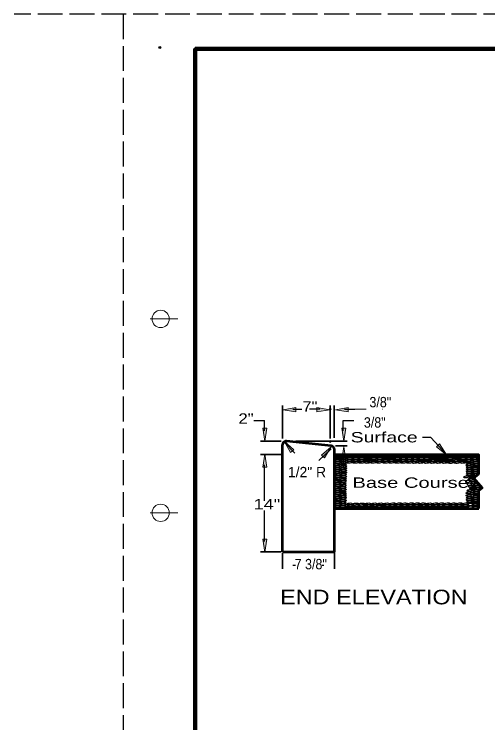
# Model space of a CAD drawing. Extents: x 75.6 to 110.9, y 28 to 50.
# Drawn here: x 75.6 to 82.44, y 39.75 to 49.98 of the extents above; entities that cross this region are included whole.
import ezdxf

# ---------------------------------------------------------------- set-up
doc = ezdxf.new("R2010")
doc.units = 0
doc.header["$LTSCALE"] = 0.06
doc.header["$PDMODE"] = 32
doc.header["$PDSIZE"] = 0.03
doc.linetypes.add('LONG_DASHED', pattern=[7.5, 6, -1.5])
doc.layers.add('1', color=7, linetype='Continuous', lineweight=25)
doc.layers.add('3', color=7, linetype='Continuous', lineweight=13)

msp = doc.modelspace()

# ---------------------------------------------------------------- hatches: boundary and pattern name
at = {"layer": '3'}
for points in [[(79.67092, 44.3), (79.67092, 44.2385), (79.48633, 44.26933), (79.48633, 44.26933)], [(79.97408, 44.3), (79.97408, 44.2385), (80.15867, 44.26933), (80.15867, 44.26933)], [(80.42625, 44.3), (80.42625, 44.2385), (80.24167, 44.26933), (80.24167, 44.26933)], [(79.19092, 44.00033), (79.25242, 44.00033), (79.22158, 43.81575), (79.22158, 43.81575)], [(80.39358, 44.00033), (80.33208, 44.00033), (80.36292, 43.81575), (80.36292, 43.81575)], [(79.594, 43.65142), (79.64158, 43.69058), (79.5005, 43.81358), (79.5005, 43.81358)], [(80.08542, 43.57192), (80.03875, 43.61192), (80.18192, 43.73242), (80.18192, 43.73242)], [(80.39358, 43.547), (80.33208, 43.547), (80.36292, 43.73158), (80.36292, 43.73158)], [(81.69967, 43.73425), (81.74517, 43.77558), (81.84642, 43.61825), (81.84642, 43.61825)], [(79.19092, 43.44117), (79.25242, 43.44117), (79.22158, 43.62575), (79.22158, 43.62575)], [(79.19092, 42.39817), (79.25242, 42.39817), (79.22158, 42.21358), (79.22158, 42.21358)], [(79.19092, 42.39817), (79.25242, 42.39817), (79.22158, 42.21358), (79.22158, 42.21358)]]:
    msp.add_hatch(color=256, dxfattribs=at).paths.add_polyline_path(points)

# ---------------------------------------------------------------- linework, layer by layer
at = {"layer": '1', "linetype": 'LONG_DASHED'}
for p, q in [((110.8, 49.97992), (75.6, 49.97992)), ((77.175, 49.97992), (77.175, 27.97992))]:
    msp.add_line(p, q, dxfattribs=at)
at = {"layer": '1', "lineweight": 158}
for p, q in [((78.21667, 49.47992), (78.21667, 28.47992)), ((110.71667, 49.47992), (78.21667, 49.47992))]:
    msp.add_line(p, q, dxfattribs=at)
at = {"layer": '1', "lineweight": 13}
for p, q in [((77.96667, 45.57992), (77.56667, 45.57992)), ((80.226, 43.61183), (82.31042, 43.61183)), ((80.226, 43.58358), (82.31042, 43.58358)), ((77.96667, 42.77992), (77.56667, 42.77992))]:
    msp.add_line(p, q, dxfattribs=at)
at = {"layer": '1', "lineweight": 53}
for p, q in [((80.1775, 43.74758), (79.53667, 43.8145)), ((79.47725, 42.21767), (79.47725, 43.76075)), ((80.226, 43.59875), (82.31042, 43.59875)), ((82.3115, 42.83717), (80.22708, 42.83717))]:
    msp.add_line(p, q, dxfattribs=at)
for points in [[(79.47725, 42.21767), (80.226, 42.21767), (80.226, 43.69392)], [(80.226, 43.62408), (82.31042, 43.62408), (82.31042, 43.33558)], [(82.31042, 43.33558), (82.24275, 43.27817), (82.36375, 43.14133), (82.31042, 43.09667), (82.31042, 42.84492)]]:
    msp.add_lwpolyline(points, dxfattribs=at)
at = {"layer": '1', "lineweight": 13}
for centre in [(77.71667, 45.57992), (77.71667, 42.77992)]:
    msp.add_circle(centre, 0.125, dxfattribs=at)
at = {"layer": '1', "lineweight": 53}
for centre, start, end in [((79.53125, 43.76075), 84.18493, 180), ((80.172, 43.6939), 0, 84.18493)]:
    msp.add_arc(centre, 0.054, start, end, dxfattribs=at)
at = {"layer": '1'}
for centre, major_axis, ratio in [((80.26817, 43.47475), (0.04401, 0.00432), 0.308638), ((80.27033, 43.536), (0.04401, 0.00432), 0.308638), ((80.27033, 43.50542), (0.04401, 0.00432), 0.308638), ((80.27133, 43.56667), (0.04401, 0.00432), 0.308638), ((80.35475, 43.56567), (0.04401, 0.00432), 0.308638), ((80.35683, 43.53608), (0.04401, 0.00432), 0.308638), ((80.35683, 43.50758), (0.04401, 0.00432), 0.308638), ((80.35683, 43.48008), (0.04401, 0.00432), 0.308638), ((80.44442, 43.56775), (0.04401, 0.00432), 0.308638), ((80.4455, 43.53925), (0.04401, 0.00432), 0.308638), ((80.4465, 43.51075), (0.04401, 0.00432), 0.308638), ((80.532, 43.56775), (0.04401, 0.00432), 0.308638), ((80.532, 43.50975), (0.04401, 0.00432), 0.308638), ((80.53308, 43.53925), (0.04401, 0.00432), 0.308638), ((80.61858, 43.56775), (0.04401, 0.00432), 0.308638), ((80.61858, 43.50975), (0.04401, 0.00432), 0.308638), ((80.61958, 43.53925), (0.04401, 0.00432), 0.308638), ((80.70408, 43.56667), (0.04401, 0.00432), 0.308638), ((80.70408, 43.50867), (0.04401, 0.00432), 0.308638), ((80.70508, 43.53817), (0.04401, 0.00432), 0.308638), ((80.79058, 43.53817), (0.04401, 0.00432), 0.308638), ((80.79167, 43.56775), (0.04401, 0.00432), 0.308638), ((80.79267, 43.51075), (0.04401, 0.00432), 0.308638), ((80.87717, 43.56775), (0.04401, 0.00432), 0.308638), ((80.87925, 43.53925), (0.04401, 0.00432), 0.308638), ((80.88133, 43.51183), (0.04401, 0.00432), 0.308638), ((80.96158, 43.56667), (0.04401, 0.00432), 0.308638), ((80.96475, 43.54025), (0.04401, 0.00432), 0.308638), ((80.96683, 43.50975), (0.04401, 0.00432), 0.308638), ((81.046, 43.56667), (0.04401, 0.00432), 0.308638), ((81.05025, 43.53925), (0.04401, 0.00432), 0.308638), ((81.05342, 43.51075), (0.04401, 0.00432), 0.308638), ((81.13258, 43.56775), (0.04401, 0.00432), 0.308638), ((81.13575, 43.53817), (0.04401, 0.00432), 0.308638), ((81.13992, 43.50975), (0.04401, 0.00432), 0.308638), ((81.217, 43.56775), (0.04401, 0.00432), 0.308638), ((81.22017, 43.54025), (0.04401, 0.00432), 0.308638), ((81.22333, 43.50975), (0.04401, 0.00432), 0.308638), ((81.30675, 43.56783), (0.04401, 0.00432), 0.308638), ((81.30883, 43.53933), (0.04401, 0.00432), 0.308638), ((81.30992, 43.50975), (0.04401, 0.00432), 0.308638), ((81.39117, 43.50875), (0.04401, 0.00432), 0.308638), ((81.39325, 43.53933), (0.04401, 0.00432), 0.308638), ((81.39433, 43.56892), (0.04401, 0.00432), 0.308638), ((81.47875, 43.50875), (0.04401, 0.00432), 0.308638), ((81.48083, 43.56783), (0.04401, 0.00432), 0.308638), ((81.48083, 43.53825), (0.04401, 0.00432), 0.308638), ((81.56425, 43.50875), (0.04401, 0.00432), 0.308638), ((81.56525, 43.53825), (0.04401, 0.00432), 0.308638), ((81.56633, 43.56575), (0.04401, 0.00432), 0.308638), ((81.65183, 43.56683), (0.04401, 0.00432), 0.308638), ((81.65183, 43.53933), (0.04401, 0.00432), 0.308638), ((81.65183, 43.50875), (0.04401, 0.00432), 0.308638), ((81.73625, 43.56683), (0.04401, 0.00432), 0.308638), ((81.73733, 43.53825), (0.04401, 0.00432), 0.308638), ((81.73842, 43.50875), (0.04401, 0.00432), 0.308638), ((81.82175, 43.56683), (0.04401, 0.00432), 0.308638), ((81.82283, 43.53825), (0.04401, 0.00432), 0.308638), ((81.82383, 43.50875), (0.04401, 0.00432), 0.308638), ((81.90617, 43.56575), (0.04401, 0.00432), 0.308638), ((81.90933, 43.53825), (0.04401, 0.00432), 0.308638), ((81.91042, 43.50767), (0.04401, 0.00432), 0.308638), ((81.99483, 43.56683), (0.04401, 0.00432), 0.308638), ((81.998, 43.53725), (0.04401, 0.00432), 0.308638), ((82.00008, 43.50767), (0.04401, 0.00432), 0.308638), ((82.08242, 43.56783), (0.04401, 0.00432), 0.308638), ((82.08558, 43.53825), (0.04401, 0.00432), 0.308638), ((82.08667, 43.50875), (0.04401, 0.00432), 0.308638), ((82.16792, 43.56567), (0.04401, 0.00432), 0.308638), ((82.17, 43.53508), (0.04401, 0.00432), 0.308638), ((82.17108, 43.47383), (0.04401, 0.00432), 0.308638), ((82.17217, 43.50442), (0.04401, 0.00432), 0.308638), ((82.25658, 43.56567), (0.04401, 0.00432), 0.308638), ((82.25975, 43.53608), (0.04401, 0.00432), 0.308638), ((82.263, 43.47592), (0.04401, 0.00432), 0.308638), ((82.264, 43.5055), (0.04401, 0.00432), 0.308638), ((80.27033, 43.44417), (0.04401, 0.00432), 0.308638), ((80.27033, 43.41458), (0.04401, 0.00432), 0.308638), ((80.27033, 43.38608), (0.04401, 0.00432), 0.308638), ((80.35792, 43.39033), (0.04401, 0.00432), 0.308638), ((80.359, 43.422), (0.04401, 0.00432), 0.308638), ((80.36, 43.4505), (0.04401, 0.00432), 0.308638), ((82.17425, 43.44325), (0.04401, 0.00432), 0.308638), ((82.17525, 43.41475), (0.04401, 0.00432), 0.308638), ((82.17742, 43.38617), (0.04401, 0.00432), 0.308638), ((82.264, 43.44633), (0.04401, 0.00432), 0.308638), ((82.264, 43.41675), (0.04401, 0.00432), 0.308638), ((82.26508, 43.38717), (0.04401, 0.00432), 0.308638), ((80.26925, 43.3565), (0.04401, 0.00432), 0.308638), ((80.26925, 43.327), (0.04401, 0.00432), 0.308638), ((80.27033, 43.29842), (0.04401, 0.00432), 0.308638), ((80.27133, 43.26892), (0.04401, 0.00432), 0.308638), ((80.35683, 43.32908), (0.04401, 0.00432), 0.308638), ((80.35683, 43.2985), (0.04401, 0.00432), 0.308638), ((80.35683, 43.26783), (0.04401, 0.00432), 0.308638), ((80.359, 43.35975), (0.04401, 0.00432), 0.308638), ((82.13625, 43.29958), (0.04401, 0.00432), 0.308638), ((82.17525, 43.32917), (0.04401, 0.00432), 0.308638), ((82.1795, 43.35875), (0.04401, 0.00432), 0.308638), ((82.19967, 43.26683), (0.04401, 0.00432), 0.308638), ((82.22075, 43.29742), (0.04401, 0.00432), 0.308638), ((82.25667, 43.327), (0.04401, 0.00432), 0.308638), ((82.26508, 43.35767), (0.04401, 0.00432), 0.308638), ((80.27033, 43.20867), (0.04401, 0.00432), 0.308638), ((80.27033, 43.17808), (0.04401, 0.00432), 0.308638), ((80.27133, 43.23933), (0.04401, 0.00432), 0.308638), ((80.35267, 43.20558), (0.04401, 0.00432), 0.308638), ((80.35267, 43.17283), (0.04401, 0.00432), 0.308638), ((80.35683, 43.23725), (0.04401, 0.00432), 0.308638), ((82.15167, 43.23267), (0.02825, 0.00619), 0.672605), ((82.178, 43.19258), (0.02825, 0.00619), 0.672605), ((82.225, 43.24258), (0.04401, 0.00432), 0.308638), ((82.24608, 43.21508), (0.04401, 0.00432), 0.308638), ((82.2725, 43.18975), (0.04401, 0.00432), 0.308638), ((82.29358, 43.16442), (0.04401, 0.00432), 0.308638), ((80.27033, 43.1475), (0.04401, 0.00432), 0.308638), ((80.27133, 43.11792), (0.04401, 0.00432), 0.308638), ((80.27133, 43.08725), (0.04401, 0.00432), 0.308638), ((80.35267, 43.14225), (0.04401, 0.00432), 0.308638), ((80.35267, 43.081), (0.04401, 0.00432), 0.308638), ((80.35367, 43.11158), (0.04401, 0.00432), 0.308638), ((82.17108, 43.06942), (0.04401, 0.00432), 0.308638), ((82.18583, 43.10325), (0.04401, 0.00432), 0.308638), ((82.20375, 43.16233), (0.04401, 0.00432), 0.308638), ((82.22275, 43.13383), (0.04401, 0.00432), 0.308638), ((82.263, 43.07675), (0.04401, 0.00432), 0.308638), ((82.27667, 43.10742), (0.04401, 0.00432), 0.308638), ((82.31367, 43.138), (0.04401, 0.00432), 0.308638), ((80.27033, 43.05775), (0.04401, 0.00432), 0.308638), ((80.27242, 43.02708), (0.04401, 0.00432), 0.308638), ((80.27242, 42.9965), (0.04401, 0.00432), 0.308638), ((80.27242, 42.96583), (0.04401, 0.00432), 0.308638), ((80.35367, 43.05142), (0.04401, 0.00432), 0.308638), ((80.35367, 43.02075), (0.04401, 0.00432), 0.308638), ((80.35367, 42.95958), (0.04401, 0.00432), 0.308638), ((80.35475, 42.99125), (0.04401, 0.00432), 0.308638), ((82.17208, 43.03567), (0.04401, 0.00432), 0.308638), ((82.17633, 43.00083), (0.04401, 0.00432), 0.308638), ((82.17842, 42.96917), (0.04401, 0.00432), 0.308638), ((82.264, 43.04717), (0.04401, 0.00432), 0.308638), ((82.264, 42.98808), (0.04401, 0.00432), 0.308638), ((82.26617, 43.01658), (0.04401, 0.00432), 0.308638), ((82.26717, 42.9585), (0.04401, 0.00432), 0.308638), ((80.27033, 42.87608), (0.04401, 0.00432), 0.308638), ((80.27133, 42.93417), (0.04401, 0.00432), 0.308638), ((80.27133, 42.90358), (0.04401, 0.00432), 0.308638), ((80.35158, 42.92892), (0.04401, 0.00432), 0.308638), ((80.35475, 42.90042), (0.04401, 0.00432), 0.308638), ((80.35475, 42.87292), (0.04401, 0.00432), 0.308638), ((80.4455, 42.90783), (0.04401, 0.00432), 0.308638), ((80.4455, 42.87933), (0.04401, 0.00432), 0.308638), ((80.53417, 42.87933), (0.04401, 0.00432), 0.308638), ((80.53517, 42.90683), (0.04401, 0.00432), 0.308638), ((80.62283, 42.88033), (0.04401, 0.00432), 0.308638), ((80.62383, 42.90683), (0.04401, 0.00432), 0.308638), ((80.71042, 42.90783), (0.04401, 0.00432), 0.308638), ((80.71042, 42.87933), (0.04401, 0.00432), 0.308638), ((80.799, 42.90783), (0.04401, 0.00432), 0.308638), ((80.80117, 42.87933), (0.04401, 0.00432), 0.308638), ((80.88875, 42.90783), (0.04401, 0.00432), 0.308638), ((80.88883, 42.87825), (0.04401, 0.00432), 0.308638), ((80.97742, 42.90783), (0.04401, 0.00432), 0.308638), ((80.97742, 42.87933), (0.04401, 0.00432), 0.308638), ((81.064, 42.88033), (0.04401, 0.00432), 0.308638), ((81.06608, 42.91), (0.04401, 0.00432), 0.308638), ((81.15058, 42.88033), (0.04401, 0.00432), 0.308638), ((81.15475, 42.91), (0.04401, 0.00432), 0.308638), ((81.23917, 42.90892), (0.04401, 0.00432), 0.308638), ((81.24133, 42.88042), (0.04401, 0.00432), 0.308638), ((81.32883, 42.91), (0.04401, 0.00432), 0.308638), ((81.32892, 42.8815), (0.04401, 0.00432), 0.308638), ((81.41542, 42.91), (0.04401, 0.00432), 0.308638), ((81.41542, 42.8815), (0.04401, 0.00432), 0.308638), ((81.503, 42.90892), (0.04401, 0.00432), 0.308638), ((81.50408, 42.87933), (0.04401, 0.00432), 0.308638), ((81.59275, 42.90783), (0.04401, 0.00432), 0.308638), ((81.59275, 42.87933), (0.04401, 0.00432), 0.308638), ((81.68142, 42.91), (0.04401, 0.00432), 0.308638), ((81.68142, 42.87933), (0.04401, 0.00432), 0.308638), ((81.76692, 42.88042), (0.04401, 0.00432), 0.308638), ((81.76792, 42.91), (0.04401, 0.00432), 0.308638), ((81.8555, 42.91), (0.04401, 0.00432), 0.308638), ((81.85558, 42.88258), (0.04401, 0.00432), 0.308638), ((81.94417, 42.88042), (0.04401, 0.00432), 0.308638), ((81.94525, 42.90892), (0.04401, 0.00432), 0.308638), ((82.02867, 42.8815), (0.04401, 0.00432), 0.308638), ((82.03175, 42.91), (0.04401, 0.00432), 0.308638), ((82.11942, 42.8815), (0.04401, 0.00432), 0.308638), ((82.1215, 42.91), (0.04401, 0.00432), 0.308638), ((82.18058, 42.9385), (0.04401, 0.00432), 0.308638), ((82.19183, 42.90225), (0.02825, 0.00619), 0.672605), ((82.19283, 42.861), (0.02825, 0.00619), 0.672605), ((82.26183, 42.89625), (0.04401, 0.00432), 0.308638), ((82.26292, 42.92692), (0.04401, 0.00432), 0.308638), ((82.26392, 42.8625), (0.04401, 0.00432), 0.308638), ((80.2735, 42.85075), (0.04401, 0.00432), 0.308638), ((80.359, 42.84975), (0.04401, 0.00432), 0.308638), ((80.44658, 42.85183), (0.04401, 0.00432), 0.308638), ((80.53417, 42.85292), (0.04401, 0.00432), 0.308638), ((80.62283, 42.85292), (0.04401, 0.00432), 0.308638), ((80.7115, 42.85292), (0.04401, 0.00432), 0.308638), ((80.80117, 42.85183), (0.04401, 0.00432), 0.308638), ((80.88883, 42.85075), (0.04401, 0.00432), 0.308638), ((80.97958, 42.85183), (0.04401, 0.00432), 0.308638), ((81.06717, 42.85292), (0.04401, 0.00432), 0.308638), ((81.15367, 42.85392), (0.04401, 0.00432), 0.308638), ((81.24017, 42.85183), (0.04401, 0.00432), 0.308638), ((81.32892, 42.853), (0.04401, 0.00432), 0.308638), ((81.41442, 42.853), (0.04401, 0.00432), 0.308638), ((81.50308, 42.85083), (0.04401, 0.00432), 0.308638), ((81.59067, 42.85083), (0.04401, 0.00432), 0.308638), ((81.68042, 42.85192), (0.04401, 0.00432), 0.308638), ((81.76692, 42.85192), (0.04401, 0.00432), 0.308638), ((81.8535, 42.853), (0.04401, 0.00432), 0.308638), ((81.94425, 42.85192), (0.04401, 0.00432), 0.308638), ((82.02867, 42.853), (0.04401, 0.00432), 0.308638), ((82.1205, 42.853), (0.04401, 0.00432), 0.308638)]:
    msp.add_ellipse(centre, major_axis=major_axis, ratio=ratio, dxfattribs=at)
for p in [(77.70467, 49.49992), (78.21667, 49.47992)]:
    msp.add_point(p, dxfattribs=at)
at = {"layer": '3', "lineweight": 35}
for p, q in [((79.47625, 43.8515), (79.47625, 44.32992)), ((80.16592, 43.85533), (80.16592, 44.32992)), ((80.22267, 43.86283), (80.22267, 44.32992)), ((79.4575, 43.81358), (79.16075, 43.81358)), ((79.6695, 43.81358), (80.40933, 43.81358)), ((80.24142, 43.74542), (80.40933, 43.74542)), ((79.4575, 43.62417), (79.16075, 43.62417)), ((79.4585, 42.21767), (79.16075, 42.21767)), ((79.47725, 42.19892), (79.47725, 41.97108)), ((80.226, 42.19892), (80.226, 41.97108))]:
    msp.add_line(p, q, dxfattribs=at)
at = {"layer": '3', "lineweight": 25}
for p, q in [((79.62625, 44.27592), (79.75567, 44.27592)), ((80.01592, 44.27592), (79.86592, 44.27592)), ((80.37267, 44.27592), (80.52267, 44.27592)), ((79.06475, 44.11358), (79.21475, 44.11358)), ((79.21475, 43.96358), (79.21475, 44.11358)), ((79.49808, 43.80342), (79.65433, 43.64308)), ((80.17875, 43.70492), (80.00175, 43.537)), ((80.35533, 43.59542), (80.35533, 43.44542)), ((79.21475, 42.95317), (79.21475, 43.47417)), ((79.21475, 42.36767), (79.21475, 42.81367)), ((79.62725, 42.02508), (79.66558, 42.02508)), ((80.04858, 42.02508), (80.076, 42.02508))]:
    msp.add_line(p, q, dxfattribs=at)
at = {"layer": '3'}
for p, q in [((79.91158, 44.27592), (80.01592, 44.27592)), ((80.16592, 44.25717), (80.16592, 44.22192)), ((80.22267, 44.27592), (80.22275, 44.27592)), ((80.52267, 44.27592), (80.68592, 44.27592)), ((80.91458, 44.27592), (80.92267, 44.27592)), ((79.21475, 43.81358), (79.21483, 43.81358)), ((79.47625, 43.81358), (79.47633, 43.81358)), ((79.47625, 43.81358), (79.47633, 43.81358)), ((79.47625, 43.81358), (79.47633, 43.81358)), ((80.22267, 43.80983), (80.22275, 43.80983)), ((80.22267, 43.74542), (80.22275, 43.74542)), ((80.35533, 43.74542), (80.35542, 43.74542)), ((79.21475, 43.62417), (79.21483, 43.62417)), ((79.47625, 43.62417), (79.47633, 43.62417)), ((79.47725, 42.21767), (79.47733, 42.21767)), ((79.47725, 42.21767), (79.47733, 42.21767)), ((80.226, 42.21767), (80.22608, 42.21767)), ((80.226, 42.02508), (80.22608, 42.02508))]:
    msp.add_line(p, q, dxfattribs=at)
for points in [[(79.67092, 44.3), (79.67092, 44.2385), (79.48633, 44.26933), (79.48633, 44.26933)], [(79.97408, 44.3), (79.97408, 44.2385), (80.15867, 44.26933), (80.15867, 44.26933)], [(80.42625, 44.3), (80.42625, 44.2385), (80.24167, 44.26933), (80.24167, 44.26933)], [(79.19092, 44.00033), (79.25242, 44.00033), (79.22158, 43.81575), (79.22158, 43.81575)], [(80.39358, 44.00033), (80.33208, 44.00033), (80.36292, 43.81575), (80.36292, 43.81575)], [(79.594, 43.65142), (79.64158, 43.69058), (79.5005, 43.81358), (79.5005, 43.81358)], [(80.08542, 43.57192), (80.03875, 43.61192), (80.18192, 43.73242), (80.18192, 43.73242)], [(80.39358, 43.547), (80.33208, 43.547), (80.36292, 43.73158), (80.36292, 43.73158)], [(81.69967, 43.73425), (81.74517, 43.77558), (81.84642, 43.61825), (81.84642, 43.61825)], [(79.19092, 43.44117), (79.25242, 43.44117), (79.22158, 43.62575), (79.22158, 43.62575)], [(79.19092, 42.39817), (79.25242, 42.39817), (79.22158, 42.21358), (79.22158, 42.21358)], [(79.19092, 42.39817), (79.25242, 42.39817), (79.22158, 42.21358), (79.22158, 42.21358)]]:
    msp.add_lwpolyline(points, close=True, dxfattribs=at)
at = {"layer": '3', "lineweight": 25}
for points in [[(80.35533, 43.96358), (80.35533, 44.11358), (80.50533, 44.11358)], [(81.84542, 43.62408), (81.62133, 43.86942), (81.50008, 43.86942)]]:
    msp.add_lwpolyline(points, dxfattribs=at)
at = {"layer": '3'}
for p in [(80.16592, 44.27592), (80.16592, 43.80983)]:
    msp.add_point(p, dxfattribs=at)

# ---------------------------------------------------------------- texts
for s, height, width, p in [('3/8"', 0.15, 0.9, (80.7325, 44.30333)), ('7"', 0.15, 1.2, (79.76308, 44.24133)), ('2"', 0.15, 1.2, (78.84025, 44.06625)), ('3/8"', 0.15, 0.9, (80.65217, 44.01008)), ('Surface', 0.15, 1.4, (80.4615, 43.797)), ('Base Course ', 0.15, 1.45, (80.48725, 43.141)), ('14"', 0.15, 1.3, (79.06042, 42.8305)), ('7 3/8"', 0.15, 0.9, (79.65175, 41.96442)), ('END ELEVATION ', 0.2109, 1.2, (79.44242, 41.45883))]:
    msp.add_text(s, height=height, dxfattribs=dict(at, width=width)).set_placement(p)
msp.add_text('1/2" R', height=0.15, dxfattribs=at).set_placement((79.55558, 43.29325))

doc.saveas('drawing.dxf')
